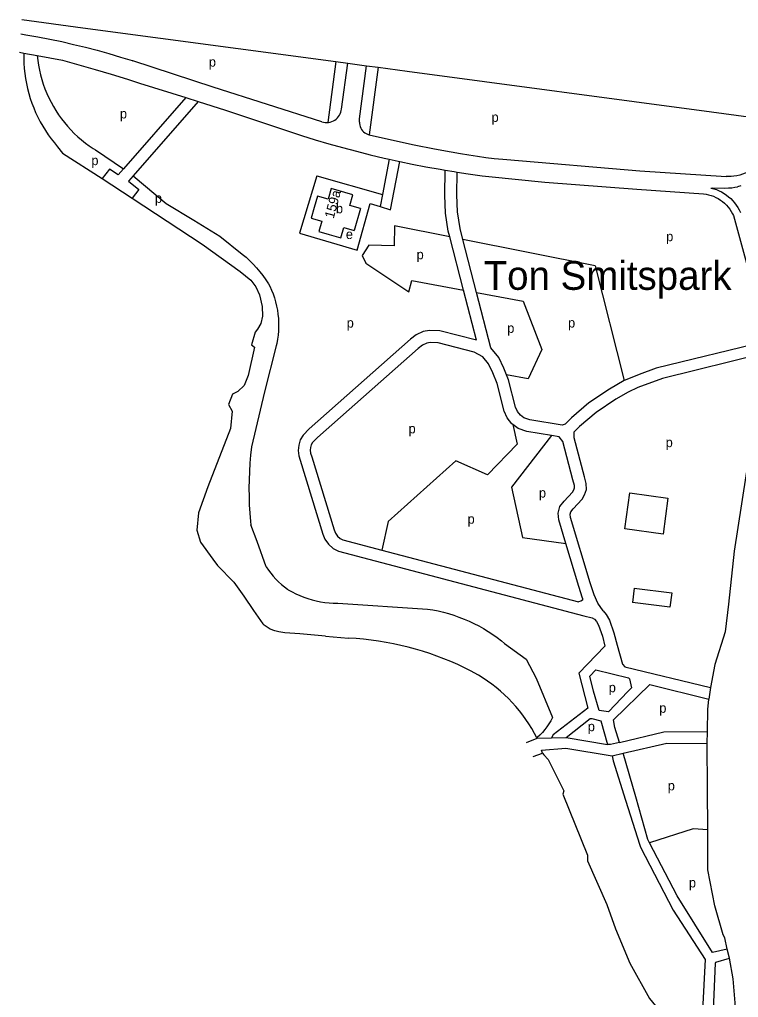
# Model space of a CAD drawing. Extents: x 161258 to 163262, y 380749 to 382054.
# Drawn here: x 161262.6 to 161562.6, y 381313.9 to 381721.7 of the extents above; entities that cross this region are included whole.
import ezdxf

# ---------------------------------------------------------------- set-up
doc = ezdxf.new("R2010")
doc.units = 0
for name, color, linetype in [('BLT_Basislijn', 7, 'Continuous'), ('BLT_Bebouwing', 7, 'Continuous'), ('BLT_Centroide', 7, 'Continuous'), ('BLT_Huisnummer', 7, 'Continuous'), ('BLT_Sport_parknaam', 7, 'Continuous')]:
    doc.layers.add(name, color=color, linetype=linetype)

msp = doc.modelspace()

# ---------------------------------------------------------------- linework, layer by layer
at = {"layer": 'BLT_Basislijn'}
for p, q in [((161263.59, 381721.7), (161289.05, 381718.25)), ((161289.05, 381718.25), (161353.75, 381709.6)), ((161264.39, 381707.7), (161269.97, 381706.66)), ((161269.97, 381706.66), (161280.46, 381704.7)), ((161353.75, 381709.6), (161394.59, 381704.18)), ((161394.59, 381704.18), (161391.18, 381678.76)), ((161394.59, 381704.18), (161399.5, 381703.52)), ((161396.93, 381684.38), (161399.5, 381703.52)), ((161399.5, 381703.52), (161407.42, 381702.47)), ((161407.42, 381702.47), (161412.2, 381701.84)), ((161412.2, 381701.84), (161408.41, 381673.69)), ((161412.2, 381701.84), (161424.35, 381700.22)), ((161424.35, 381700.22), (161551.26, 381683.18)), ((161312.57, 381695.23), (161331.91, 381689.16)), ((161331.91, 381689.16), (161305.91, 381659.48)), ((161337.12, 381687.52), (161309.99, 381656.54)), ((161331.91, 381689.16), (161337.12, 381687.52)), ((161551.26, 381683.18), (161639.13, 381671.6)), ((161407.98, 381673.8), (161408.41, 381673.69)), ((161294.21, 381667.32), (161305.91, 381659.48)), ((161416.79, 381663.5), (161413.96, 381648.79)), ((161465.95, 381663.36), (161521.45, 381658.64)), ((161300.15, 381659.38), (161297.03, 381655.36)), ((161303.73, 381656.98), (161300.15, 381659.38)), ((161305.91, 381659.48), (161303.73, 381656.98)), ((161521.45, 381658.64), (161557.45, 381656.28)), ((161297.03, 381655.36), (161309.6, 381647.23)), ((161309.99, 381656.54), (161308.04, 381654.31)), ((161308.04, 381654.31), (161312.42, 381650.86)), ((161386.6, 381656.58), (161413.96, 381648.79)), ((161312.42, 381650.86), (161309.6, 381647.23)), ((161520.1, 381651.03), (161547.93, 381649)), ((161563.59, 381652.36), (161562.2, 381651.98)), ((161560.44, 381639.98), (161571.71, 381598.71)), ((161442.09, 381631.11), (161418.97, 381635.71)), ((161502.77, 381619.05), (161447.53, 381630.03)), ((161502.77, 381619.05), (161514.83, 381571.14)), ((161519.08, 381484.6), (161518.32, 381478.67)), ((161519.08, 381484.6), (161534.74, 381482.62)), ((161534.74, 381482.62), (161533.99, 381476.69)), ((161395.38, 381478.32), (161432.76, 381475.9)), ((161533.99, 381476.69), (161518.32, 381478.67)), ((161390.25, 381464.55), (161399.89, 381463.74)), ((161550.87, 381443.13), (161550.19, 381438.36)), ((161474.11, 381420.23), (161478.55, 381422.06)), ((161478.55, 381422.06), (161478.48, 381422.2)), ((161478.55, 381422.06), (161484.49, 381422.24)), ((161484.49, 381422.24), (161490.69, 381422.38)), ((161490.69, 381422.38), (161507.96, 381419.43)), ((161549.52, 381419.86), (161549.58, 381424.77)), ((161549.63, 381400.88), (161549.52, 381419.86)), ((161476.9, 381414.37), (161480.73, 381415.84)), ((161509.87, 381414.66), (161514.51, 381415.76)), ((161519.69, 381397.54), (161514.51, 381415.76)), ((161549.73, 381383.8), (161549.63, 381400.88)), ((161515.49, 381396.26), (161521.43, 381377.47)), ((161558.8, 381330.26), (161557.92, 381334.05))]:
    msp.add_line(p, q, dxfattribs=at)
for points in [[(161263.14, 381715.74), (161265.24, 381715.4), (161270.23, 381714.51), (161275.2, 381713.54), (161280.16, 381712.49), (161285.11, 381711.36), (161290.03, 381710.16), (161294.94, 381708.88), (161299.82, 381707.52), (161304.68, 381706.08), (161309.52, 381704.57), (161309.78, 381704.49)], [(161262.57, 381708.04), (161264.39, 381707.7)], [(161264.39, 381707.7), (161264.37, 381705.57), (161264.42, 381703.45), (161264.56, 381701.33), (161264.77, 381699.21), (161265.07, 381697.1), (161265.44, 381695.01), (161265.89, 381692.93), (161266.42, 381690.87), (161267.03, 381688.84), (161267.71, 381686.82), (161268.47, 381684.83), (161269.3, 381682.88), (161270.21, 381680.95), (161271.18, 381679.06), (161272.23, 381677.21), (161273.35, 381675.4), (161274.53, 381673.64), (161275.78, 381671.92), (161277.1, 381670.24), (161278.45, 381668.65)], [(161269.97, 381706.66), (161270.2, 381704.63), (161270.5, 381702.62), (161270.88, 381700.62), (161271.35, 381698.63), (161271.88, 381696.67), (161272.5, 381694.73), (161273.19, 381692.81), (161273.96, 381690.92), (161274.8, 381689.06), (161275.71, 381687.24), (161276.69, 381685.46), (161277.74, 381683.71), (161278.86, 381682.01), (161280.05, 381680.35), (161281.3, 381678.74), (161282.61, 381677.18), (161283.98, 381675.68), (161285.41, 381674.23), (161286.9, 381672.83), (161288.44, 381671.5), (161290.03, 381670.22), (161291.67, 381669.02), (161293.35, 381667.87), (161294.21, 381667.32)], [(161280.46, 381704.7), (161287.27, 381702.84), (161294.06, 381700.91), (161300.83, 381698.91), (161307.58, 381696.82), (161312.57, 381695.23)], [(161388.73, 381679.04), (161343.34, 381693.55), (161309.78, 381704.49)], [(161404.4, 381678.97), (161404.41, 381680.32), (161407.42, 381702.47)], [(161337.12, 381687.52), (161348.51, 381683.95), (161380.28, 381673.35)], [(161391.18, 381678.76), (161391.52, 381678.78), (161392.22, 381678.92), (161392.89, 381679.13), (161393.54, 381679.41), (161394.15, 381679.77), (161394.72, 381680.19), (161395.24, 381680.68), (161395.7, 381681.22), (161396.09, 381681.8), (161396.42, 381682.43), (161396.67, 381683.1), (161396.85, 381683.78), (161396.93, 381684.38)], [(161388.73, 381679.04), (161389.41, 381678.86), (161390.11, 381678.75), (161390.82, 381678.73), (161391.18, 381678.76)], [(161404.4, 381678.97), (161404.42, 381678.32), (161404.52, 381677.68), (161404.7, 381677.05), (161404.96, 381676.45), (161405.28, 381675.89), (161405.67, 381675.37), (161406.13, 381674.9), (161406.63, 381674.49), (161407.19, 381674.15), (161407.78, 381673.87), (161407.98, 381673.8)], [(161408.41, 381673.69), (161410.22, 381673.25), (161427.19, 381669.43), (161435.72, 381667.8), (161442.75, 381666.51), (161446.61, 381665.91)], [(161380.28, 381673.35), (161385.97, 381671.6), (161391.67, 381669.92), (161397.4, 381668.31), (161403.15, 381666.79), (161408.92, 381665.34), (161414.71, 381663.97), (161416.79, 381663.5)], [(161278.45, 381668.65), (161280.54, 381666.05), (161297.03, 381655.36)], [(161446.61, 381665.91), (161450.11, 381665.27), (161453.63, 381664.71), (161457.15, 381664.22), (161460.69, 381663.81), (161464.24, 381663.49), (161465.95, 381663.36)], [(161412.99, 381643.73), (161417.32, 381642.38), (161421.3, 381662.51)], [(161416.79, 381663.5), (161420.52, 381662.67), (161421.3, 381662.51)], [(161421.3, 381662.51), (161426.34, 381661.46), (161432.18, 381660.32), (161438.04, 381659.26), (161440.23, 381658.9)], [(161442.09, 381631.11), (161441.47, 381633.51), (161440.29, 381641.01), (161440.02, 381648.54), (161440.23, 381658.9)], [(161440.23, 381658.9), (161443.9, 381658.28), (161445.21, 381658.08)], [(161447.53, 381630.03), (161446.37, 381634.52), (161445.28, 381641.49), (161445.03, 381648.58), (161445.21, 381658.08)], [(161445.21, 381658.08), (161449.79, 381657.38), (161455.68, 381656.56), (161458.36, 381656.22)], [(161568.62, 381659.32), (161567.58, 381658.68), (161566.5, 381658.11), (161565.39, 381657.62), (161564.25, 381657.2), (161563.08, 381656.85), (161561.89, 381656.59), (161560.69, 381656.4), (161559.48, 381656.29), (161558.26, 381656.26), (161557.45, 381656.28)], [(161309.99, 381656.54), (161323.74, 381645.01), (161335.3, 381638.11)], [(161386.6, 381656.58), (161379.45, 381632.62), (161403.41, 381625.48), (161408.87, 381645.02), (161412.99, 381643.73)], [(161458.36, 381656.22), (161481.8, 381653.96), (161520.1, 381651.03)], [(161551.1, 381651.44), (161551.56, 381651.53), (161556.7, 381651.43), (161558.43, 381651.47), (161559.75, 381651.59), (161561.04, 381651.75), (161562.2, 381651.98)], [(161551.1, 381651.44), (161552.24, 381651.14), (161553.37, 381650.77), (161554.46, 381650.32), (161555.52, 381649.8), (161556.55, 381649.2), (161557.53, 381648.54), (161558.46, 381647.82), (161559.35, 381647.03), (161560.18, 381646.18), (161560.95, 381645.29), (161561.65, 381644.34), (161562.3, 381643.34), (161562.87, 381642.31), (161563.35, 381641.28)], [(161309.6, 381647.23), (161338.78, 381628.07), (161354.62, 381616.68), (161359.13, 381613.01), (161361.22, 381610.22), (161362.77, 381606.88), (161363.75, 381602.1), (161364, 381597.99), (161363.25, 381594.99), (161361.86, 381592.58), (161360.92, 381591.34), (161359.32, 381586.07), (161360.57, 381585.12), (161358.04, 381573.22), (161356.31, 381569.13), (161353.71, 381566.59), (161351.44, 381565.55), (161349.71, 381561.19), (161351.3, 381558.36), (161350.56, 381551.17), (161341.15, 381526.85), (161337.23, 381515.97), (161336.55, 381508.73), (161338.13, 381503.75), (161343.23, 381496.75), (161345.23, 381493.99), (161351.98, 381487.13), (161356.19, 381481.32), (161360.13, 381475.35), (161364.07, 381469.7)], [(161413.96, 381648.79), (161412.99, 381643.73)], [(161547.93, 381649), (161549.02, 381648.87), (161550.09, 381648.65), (161551.15, 381648.36), (161552.18, 381648), (161553.19, 381647.56), (161554.15, 381647.04), (161555.08, 381646.46), (161555.97, 381645.81), (161556.8, 381645.1), (161557.58, 381644.33), (161558.3, 381643.51), (161558.96, 381642.64), (161559.55, 381641.71), (161560.08, 381640.75), (161560.44, 381639.98)], [(161335.3, 381638.11), (161346.2, 381631.4), (161355.51, 381623.94)], [(161418.97, 381635.71), (161418.85, 381627.33), (161408.29, 381627.66), (161405.59, 381623.3), (161407.09, 381620.1), (161424.99, 381608.18), (161426.31, 381612.91), (161447.84, 381608.88)], [(161447.84, 381608.88), (161442.09, 381631.11)], [(161453.27, 381607.86), (161447.53, 381630.03)], [(161355.51, 381623.94), (161357.08, 381622.58), (161358.6, 381621.16), (161360.06, 381619.68), (161361.46, 381618.15), (161362.8, 381616.56), (161364.08, 381614.93), (161365.29, 381613.24), (161366.44, 381611.51), (161367.06, 381610.52)], [(161367.06, 381610.52), (161367.77, 381608.92), (161368.4, 381607.29), (161368.95, 381605.64), (161369.43, 381603.96), (161369.83, 381602.26), (161370.16, 381600.55), (161370.4, 381598.82), (161370.57, 381597.08), (161370.65, 381595.34), (161370.66, 381593.59), (161370.58, 381591.85), (161370.43, 381590.11), (161370.19, 381588.38), (161369.88, 381586.66), (161369.67, 381585.72)], [(161453.25, 381587.98), (161447.84, 381608.88)], [(161453.27, 381607.86), (161472.78, 381604.21), (161480.49, 381584.14), (161474.83, 381571.88), (161465.82, 381573.5)], [(161459.24, 381584.81), (161453.27, 381607.86)], [(161453.25, 381587.98), (161438.01, 381591.87), (161433.63, 381592.1), (161431.01, 381591.62), (161428.08, 381590.28), (161425.73, 381588.43), (161383.46, 381551.04), (161380.89, 381548.39), (161379.66, 381546.39), (161379.05, 381544.18), (161378.84, 381541.96), (161379.15, 381539.79), (161379.69, 381537.95), (161389.1, 381507.15), (161389.99, 381505.09), (161391.51, 381502.97), (161393.47, 381501.15), (161395.66, 381500.01), (161498.1, 381473.12), (161501.48, 381472.23), (161502.48, 381471.65), (161503.3, 381470.7), (161504.16, 381469.19), (161505.8, 381464.56), (161506.84, 381460.42)], [(161369.67, 381585.72), (161364.74, 381566.51), (161359.33, 381543.58)], [(161468.48, 381552.84), (161468.05, 381553.17), (161466.09, 381555.65), (161464.85, 381558.43), (161461.85, 381569.88), (161460.12, 381574.4), (161458.3, 381578.1), (161455.88, 381581.02), (161452.29, 381583.07), (161437.26, 381586.9), (161433.95, 381587.08), (161432.53, 381586.82), (161430.7, 381585.98), (161428.93, 381584.59), (161386.92, 381547.42), (161384.86, 381545.3), (161384.29, 381544.37), (161383.99, 381543.27), (161383.87, 381542.08), (161384.05, 381540.85), (161384.48, 381539.39), (161393.8, 381508.88), (161394.37, 381507.57), (161395.28, 381506.29), (161396.39, 381505.27), (161397.47, 381504.7), (161413.79, 381500.42)], [(161465.82, 381573.5), (161464.71, 381576.4), (161462.52, 381580.84), (161459.24, 381584.81)], [(161573.93, 381587.52), (161528.25, 381576.35), (161521.11, 381573.74), (161515.34, 381571.29), (161514.83, 381571.14)], [(161573.5, 381582.58), (161530.8, 381572.09), (161520.53, 381568.26), (161516.5, 381566.33)], [(161573.5, 381582.58), (161560.8, 381500), (161558.43, 381477.88), (161556.99, 381466.34), (161552.69, 381452.74), (161550.87, 381443.13)], [(161514.83, 381571.14), (161508.69, 381567.63), (161500.13, 381561.83), (161492.83, 381555.63), (161490.24, 381553.04), (161488.98, 381552.64), (161475.46, 381554.79), (161473.03, 381555.65), (161471.59, 381556.76), (161470.4, 381558.26), (161469.58, 381560.09), (161466.62, 381571.42), (161465.82, 381573.5)], [(161516.5, 381566.33), (161511.34, 381563.38), (161503.16, 381557.85), (161496.22, 381551.95), (161494.07, 381549.8)], [(161468.48, 381552.84), (161470.21, 381544.66), (161457.86, 381531.82), (161444.57, 381537.76), (161416.42, 381512.42), (161413.79, 381500.42)], [(161484.55, 381548.28), (161474.22, 381549.92), (161470.61, 381551.2), (161468.48, 381552.84)], [(161484.55, 381548.28), (161467.87, 381526.74), (161472.49, 381505.7), (161490.58, 381503.18)], [(161489.25, 381545.82), (161487.78, 381547.77), (161484.55, 381548.28)], [(161506.09, 381475.12), (161503.92, 381478.32), (161502.33, 381481.84), (161500.67, 381486.85), (161492.53, 381514.11), (161492.4, 381515.47), (161492.65, 381516.38), (161493.62, 381517.68), (161497.28, 381521.65), (161498.38, 381523.49), (161499.18, 381525.69), (161499.07, 381528.2), (161498.33, 381531), (161494.04, 381547.24), (161494.07, 381549.8)], [(161359.33, 381543.58), (161358.96, 381540.13), (161358.68, 381536.68), (161358.47, 381533.22), (161358.35, 381529.75), (161358.3, 381526.29), (161358.33, 381522.82), (161358.44, 381519.36), (161358.64, 381515.9), (161358.91, 381512.44), (161359.05, 381510.95)], [(161490.58, 381503.18), (161487.6, 381513.14), (161487.34, 381515.9), (161488.08, 381518.62), (161489.78, 381520.88), (161493.25, 381524.66), (161493.84, 381525.65), (161494.14, 381526.46), (161494.1, 381527.44), (161493.49, 381529.72), (161489.25, 381545.82)], [(161365.52, 381493.53), (161361.66, 381504.05), (161359.05, 381510.95)], [(161497.5, 381480.5), (161495.9, 381485.35), (161490.58, 381503.18)], [(161413.79, 381500.42), (161495.77, 381478.9)], [(161365.52, 381493.53), (161366.42, 381492.17), (161367.38, 381490.86), (161368.41, 381489.6), (161369.49, 381488.39), (161370.64, 381487.24), (161371.84, 381486.14), (161373.09, 381485.11), (161374.39, 381484.13), (161374.7, 381483.92)], [(161374.7, 381483.92), (161376.27, 381483.04), (161377.89, 381482.23), (161379.53, 381481.5), (161381.2, 381480.83), (161382.91, 381480.25), (161384.63, 381479.74), (161386.38, 381479.3), (161388.15, 381478.95), (161389.93, 381478.67), (161391.71, 381478.48), (161393.51, 381478.36), (161395.38, 381478.32)], [(161497.5, 381480.5), (161497.52, 381479.72), (161497.47, 381479.6), (161496.78, 381479.15), (161495.77, 381478.9)], [(161432.76, 381475.9), (161435, 381475.54), (161437.23, 381475.1), (161439.44, 381474.58), (161441.63, 381473.99), (161443.8, 381473.32), (161445.94, 381472.57), (161448.06, 381471.74), (161450.15, 381470.84), (161452.2, 381469.87), (161454.22, 381468.83), (161456.2, 381467.72), (161458.14, 381466.54), (161460.03, 381465.29), (161461.88, 381463.97), (161463.69, 381462.59), (161464.97, 381461.54)], [(161506.09, 381475.12), (161507.4, 381473.59), (161508.73, 381471.29), (161510.59, 381466), (161511.9, 381460.79)], [(161390.25, 381464.55), (161379.54, 381465.5), (161373.32, 381465.97), (161370.71, 381466.33), (161369.1, 381466.82), (161367.15, 381467.57), (161365.9, 381468.36), (161364.7, 381469.22), (161364.07, 381469.7)], [(161453.86, 381448.47), (161451.09, 381449.95), (161448.28, 381451.36), (161445.44, 381452.71), (161442.56, 381453.98), (161439.65, 381455.17), (161436.72, 381456.3), (161433.76, 381457.34), (161430.77, 381458.31), (161427.75, 381459.21), (161424.72, 381460.02), (161421.66, 381460.76), (161418.59, 381461.43), (161415.5, 381462.01), (161412.4, 381462.51), (161409.28, 381462.94), (161406.16, 381463.29), (161403.03, 381463.55), (161399.89, 381463.74)], [(161464.97, 381461.54), (161473.93, 381454.97), (161478.17, 381447.05), (161484.96, 381430.67)], [(161506.84, 381460.42), (161495.92, 381449.14), (161499.73, 381434.57), (161485.23, 381423.46), (161484.49, 381422.24)], [(161511.9, 381460.79), (161514.15, 381452.96), (161515.18, 381451.8), (161550.87, 381443.13)], [(161516.46, 381441.47), (161508.3, 381433.06), (161504.4, 381433.55), (161502.05, 381441.65), (161500.61, 381447.86), (161503.09, 381450.53), (161516.69, 381447.22), (161517.11, 381446.83), (161517.97, 381443.09), (161516.46, 381441.47)], [(161478.48, 381422.2), (161477.49, 381424.07), (161476.35, 381426.04), (161475.15, 381427.98), (161473.88, 381429.86), (161472.55, 381431.71), (161471.15, 381433.5), (161469.69, 381435.24), (161468.17, 381436.93), (161466.59, 381438.57), (161464.95, 381440.15), (161463.26, 381441.67), (161461.52, 381443.14), (161459.72, 381444.54), (161457.88, 381445.87), (161455.99, 381447.14), (161454.06, 381448.34), (161453.86, 381448.47)], [(161512.93, 381420.23), (161510.93, 381426.45), (161510.39, 381429.64), (161525.56, 381444.48), (161550.19, 381438.36)], [(161549.58, 381424.77), (161549.75, 381434.04), (161550.19, 381438.36)], [(161484.96, 381430.67), (161484.25, 381429.34), (161483.47, 381428.06), (161482.63, 381426.81), (161481.72, 381425.61), (161480.75, 381424.47), (161479.72, 381423.37), (161478.63, 381422.34), (161478.48, 381422.2)], [(161490.69, 381422.38), (161500.7, 381430.25), (161501.34, 381430.22), (161505.07, 381429.23), (161507.96, 381419.43)], [(161512.93, 381420.23), (161531.39, 381424.76), (161549.58, 381424.77)], [(161480.73, 381415.84), (161480.39, 381417.12), (161490.48, 381417.92), (161509.87, 381414.66)], [(161512.93, 381420.23), (161509.18, 381419.35), (161507.96, 381419.43)], [(161514.51, 381415.76), (161532.72, 381419.91), (161549.52, 381419.86)], [(161480.73, 381415.84), (161481.29, 381415.04), (161483.1, 381413.23), (161489.67, 381400.03), (161489.21, 381398.72), (161499.64, 381373.22), (161499.53, 381370.86), (161507.66, 381352.7), (161511.28, 381342.59), (161517.2, 381328.28), (161525.38, 381313.55), (161527.96, 381310.42), (161530.09, 381306.77), (161531.06, 381303.31), (161534.6, 381278.65), (161524.06, 381247.87), (161523.42, 381240.74), (161519.93, 381233.6), (161513.05, 381219.53)], [(161509.87, 381414.66), (161510.3, 381412.62), (161515.49, 381396.26)], [(161525.45, 381378.45), (161524.72, 381379.85), (161519.69, 381397.54)], [(161549.73, 381383.8), (161543.69, 381384.3), (161525.45, 381378.45)], [(161557.92, 381334.05), (161556.83, 381338.85), (161556.2, 381340.12), (161552.76, 381352.13), (161549.82, 381367.17), (161549.73, 381383.8)], [(161521.43, 381377.47), (161521.69, 381376.67), (161535.33, 381350.38), (161548.61, 381329.74), (161545.67, 381271.22), (161543.85, 381227.59), (161543.84, 381225.25), (161545.72, 381218.5), (161546.84, 381213.16), (161523.54, 381187.43), (161521.15, 381183.45), (161520.62, 381179.39), (161513.95, 381177.03)], [(161557.92, 381334.05), (161551.8, 381332.7), (161536.92, 381356.28), (161525.45, 381378.45)], [(161561.18, 381217.69), (161551.67, 381217.27), (161551.26, 381217.86), (161548.71, 381227.26), (161553.04, 381328.21), (161553.15, 381328.61), (161558.8, 381330.26)], [(161561.18, 381217.69), (161562.01, 381258.42), (161561.21, 381311.64), (161560.34, 381321.71), (161558.8, 381330.26)]]:
    msp.add_lwpolyline(points, dxfattribs=at)
msp.add_lwpolyline([(161517.19, 381524.31), (161533.16, 381522.11), (161531.09, 381507.1), (161515.13, 381509.3)], close=True, dxfattribs=at)
at = {"layer": 'BLT_Bebouwing'}
msp.add_line((161404.82, 381642.97), (161402.23, 381633.78), dxfattribs=at)
msp.add_lwpolyline([(161404.82, 381642.97), (161400.45, 381644.2), (161401.69, 381648.59), (161392.58, 381651.21), (161391.31, 381646.82), (161386.93, 381648.08), (161385.57, 381643.27), (161384.33, 381638.88), (161388.72, 381637.63), (161387.45, 381633.26), (161391.81, 381632.01), (161396.62, 381630.63), (161397.87, 381635.03), (161402.23, 381633.78)], dxfattribs=at)

# ---------------------------------------------------------------- texts
at = {"layer": 'BLT_Centroide'}
for s, p in [('p', (161341.56, 381702.06)), ('p', (161304.45, 381680.48)), ('p', (161459.52, 381679.03)), ('p', (161292.54, 381660.98)), ('p', (161319.06, 381645.27)), ('b', (161394.58, 381640.92)), ('e', (161398.73, 381630.19)), ('p', (161532.4, 381629.27)), ('p', (161428.26, 381621.75)), ('p', (161399.09, 381593.25)), ('p', (161491.46, 381593.27)), ('p', (161466.08, 381591.07)), ('p', (161424.9, 381549.15)), ('p', (161532.19, 381543.4)), ('p', (161479.31, 381522.37)), ('p', (161449.52, 381511.48)), ('p', (161508.44, 381441.2)), ('p', (161529.53, 381432.65)), ('p', (161499.69, 381424.95)), ('p', (161533.07, 381400.29)), ('p', (161541.88, 381359.82))]:
    msp.add_text(s, height=4, dxfattribs=at).set_placement(p)
at = {"layer": 'BLT_Huisnummer'}
msp.add_text('159a', height=4, rotation=75, dxfattribs=at).set_placement((161393.64, 381638.47))
at = {"layer": 'BLT_Sport_parknaam'}
msp.add_text('Ton Smitspark', height=12, dxfattribs=at).set_placement((161456.24, 381609))

doc.saveas('drawing.dxf')
